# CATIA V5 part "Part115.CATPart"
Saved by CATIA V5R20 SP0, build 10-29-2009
Part number: 9FA 063212
Revision: ANY
Definition: UNKNOWN
Nomenclature: 9FA 063212
Source: Unknown
Bounding box of the stored display mesh (mm): x -3 to 3, y -9.95 to 10.05, z -3 to 3
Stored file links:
  C:\Users\Utente\Desktop\IO LAVORO\3D X SITO CF\CUMSA\3D files FA\FA 063212-21\Part115.CATPart

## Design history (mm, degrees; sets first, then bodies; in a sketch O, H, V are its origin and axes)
Body1 "Cortar-Extruir5" (main body)
  Solid1: solid without history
